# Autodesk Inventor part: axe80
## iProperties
Shininess: 21.0
Length Units: 11269
Angle Units: 11279
Time Units: 11290
Mass Units: 11283
Length Display Precision: 3
Angle Display Precision: 2
Compacted: True
Created: 2001-12
Part Number: axe80
Material: Par défaut
Document SubType Name: Modélisation
Designer: pichon
Density: 0.0
Volumn: 0.0
Area: 0.0
PropertySet Name: Model Information
Control State: 0
Master: False
Checked Out: False
Author: pichon
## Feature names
1. Révolution1 [Revolution]
